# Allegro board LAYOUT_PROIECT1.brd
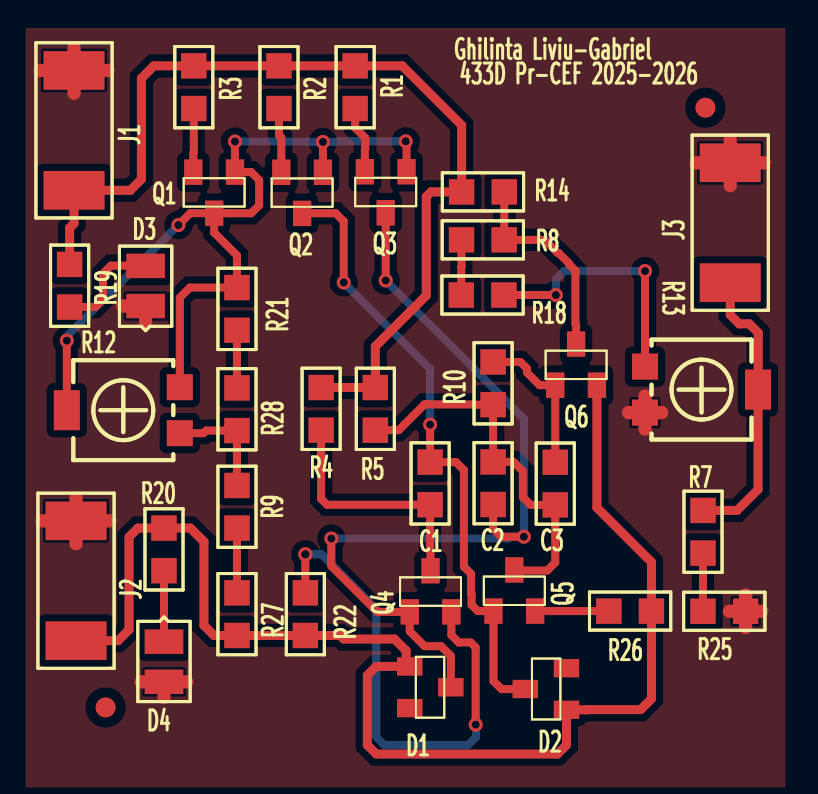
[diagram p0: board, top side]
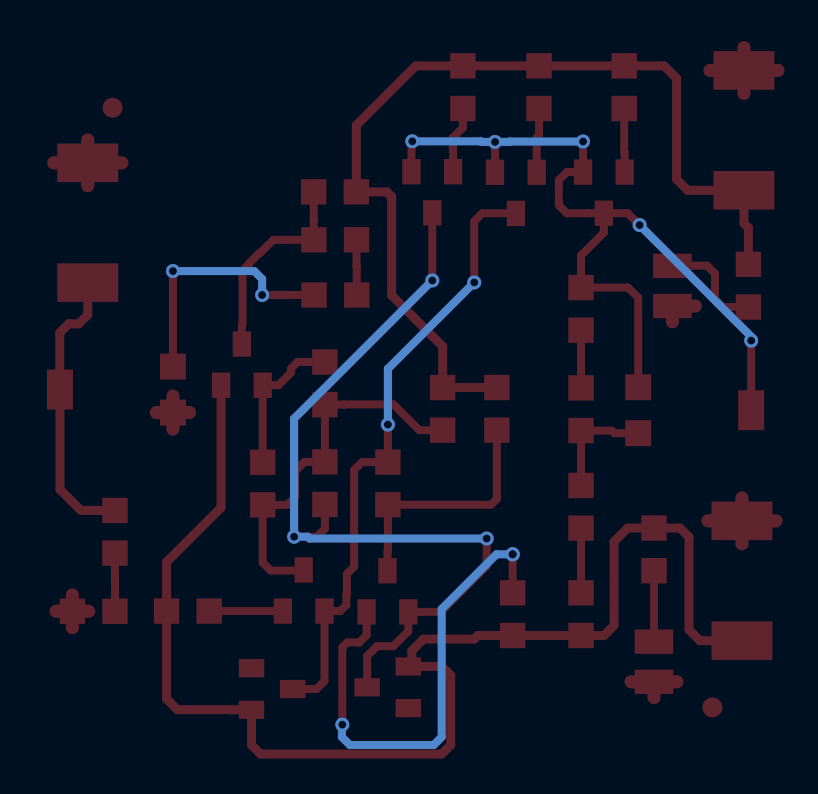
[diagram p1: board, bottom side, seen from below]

No outline. copper layers: TOP, BOTTOM. Coordinates in mm from the lowest, leftmost part position.

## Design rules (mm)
nets with their own width: min track width 0.4; nets N103383 N103451 N103463 N103557 N103581 N103587 N103701 N103715 N103835 N103897 N103911 N103917 N104055 N104249 N104493 N105640 N1034391 N1036391 N1041651 N1042051
nets with their own width: min track width 0.45; nets OUT+ V+ V-
nets with their own width: min track width 0.66; nets GND

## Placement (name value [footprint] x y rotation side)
C1  2.2n  [SMC0805]  18.03 10.26 90 top
C2  2.2n  [SMC0805]  21.18 10.27 90 top
C3  100p  [SMC0805]  24.29 10.25 90 top
D1  BZX84-C5V6  [TO236AA]  17.01 2.17 180 top
D2  BZX84-C5V6  [TO236AA]  24.85 0 0 top
D3  5V,LED,LED  [SMD0805]  3.8 20.2 90 top
D4  5V,LED,LED  [SMD0805]  4.72 3.41 270 top
J1  CON2  [SMR2512]  0.22 25.99 90 top
J2  CON2  [SMR2512]  0.32 3.46 90 top
J3  CON2  [SMR2512]  33.04 21.37 90 top
NOREF  -  [unnamed]  1.8 0.12 0 top
NOREF#2  -  [unnamed]  31.8 30.12 0 top
Q1  QBC856B  [TO236AA]  8.27 26.9 90 top
Q2  QBC856B  [TO236AA]  12.67 26.89 90 top
Q3  QBC856B  [TO236AA]  16.85 26.92 90 top
Q4  QBC846B  [TO236AA]  17.01 4.9 270 top
Q5  QBC846B  [TO236AA]  21.2 4.94 270 top
Q6  QBC846B  [TO236AA]  24.29 16.24 270 top
R1  2k  [SMR0805]  14.28 30.08 90 top
R2  2k  [SMR0805]  10.47 30.08 90 top
R3  1.5k  [SMR0805]  6.21 30.08 90 top
R4  2k  [SMR0805]  12.58 13.99 90 top
R5  2k  [SMR0805]  15.29 13.99 90 top
R7  15k  [SMR0805]  31.68 7.84 90 top
R8  9.1k  [SMR0805]  19.6 23.51 0 top
R9  15k  [SMR0805]  8.37 9.09 90 top
R10  10k  [SMR0805]  21.18 17.4 270 top
R12  500k  [TS53YL]  5.51 16.14 0 top
R13  10K  [TS53YL]  28.78 14.87 180 top
R14  2k  [SMR0805]  21.74 25.91 180 top
R18  10k  [SMR0805]  21.72 20.75 180 top
R19  220  [SMR0805]  0 20.15 90 top
R20  220  [SMR0805]  4.72 6.96 90 top
R21  150k  [SMR0805]  8.37 18.99 90 top
R22  33  [SMR0805]  11.79 3.72 90 top
R25  1k  [SMR0805]  33.81 4.93 180 top
R26  33  [SMR0805]  29.1 4.94 180 top
R27  2.7k  [SMR0805]  8.37 3.72 90 top
R28  10k  [SMR0805]  8.37 13.97 90 top

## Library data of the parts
C1-C3 = C
D1 D2 = BZX84-C5V6_9
D3 D4 = LED_5
J1-J3 = CON2
Q1-Q3 = QBC856B_0
Q4-Q6 = QBC846B_0
R1-R5 R7-R10 R14 R18-R22 R25-R28 = R
R12 R13 = POT_0

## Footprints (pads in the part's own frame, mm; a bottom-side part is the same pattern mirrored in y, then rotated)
SMC0805
  rect 1.27x1.27 smd: 1(0,0) 2(2.134,0)
SMD0805
  rect 1.219x1.93 smd: A(2.007,0) C(0,0)
SMR0805
  rect 1.27x1.27 smd: 1(0,0) 2(2.134,0)
SMR2512
  rect 1.93x3.048 smd: 1(0,0) 2(5.994,0)
TO236AA
  rect 1.27x0.914 smd: 1(0,0) 2(0,2.083) 3(-2.057,1.041)
TS53YL
  rect 1.3x1.3 smd: 1(0,0) 3(0,-2.3)
  rect 1.3x2 smd: 2(-5.65,-1.15)
unnamed
  round 1 smd: (0,0)

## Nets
GND: D3.C D4.A J1.2 J2.2 J3.2 R13.1 R25.1
OUT+: J3.1 R7.2 R13.2(WIPER)
V+: J1.1 R1.2 R2.2 R3.2 R4.2 R5.2 R14.2 R19.2
V-: D1.1 D2.1 J2.1 Q6.2(E) R20.2 R22.1 R26.1 R27.1
N103383: D3.A R19.1
N103451: Q3.2(E) R1.1
N103463: Q2.2(E) R2.1
N103557: Q1.1 Q1.3 Q2.1 Q3.1 R12.1 R12.2(WIPER) R21.2
N103581: C1.2 D2.3(C) Q2.3 Q5.1
N103587: C2.1 D1.3(C) Q3.3 Q4.1
N103701: Q6.3 R8.2 R14.1
N103715: R13.3 R18.1
N103835: R21.1 R28.2
N103897: C2.2 C3.1 Q5.3 R5.1 R10.2
N103911: R9.2 R12.3 R28.1
N103917: C1.1 Q4.3 R4.1
N104055: C3.2 Q6.1 R10.1
N104249: R7.1 R25.2
N104493: D4.C R20.1
N105640: Q4.2(E) R22.2
N1034391: Q1.2(E) R3.1
N1036391: R8.1 R18.2
N1041651: Q5.2(E) R26.2
N1042051: R9.1 R27.2

Pads without a net: D1 2; D2 2

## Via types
v1: diameter 0.7, hole 0.4, TOP to BOTTOM, 15 vias

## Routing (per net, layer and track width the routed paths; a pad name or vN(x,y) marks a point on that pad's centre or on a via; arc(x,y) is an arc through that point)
GND: length 28.6
  TOP w0.66: 31.34,27.36 J3.2 ; J3.2 34.74,27.36 ; J3.2 33.04,28.51 ; J3.2 33.04,26.22 ; 0.22,30.84 J1.2 ; J1.2 1.92,31.98 ; J1.2 0.22,33.13 ; J1.2 -1.48,31.98 ; R13.1 29.61,14.87 ; R13.1 28.78,14.04 ; R13.1 27.95,14.87 ; R13.1 28.78,15.7 ; -1.38,9.45 J2.2 ; J2.2 2.02,9.45 ; J2.2 0.32,8.31 ; J2.2 0.32,10.6 ; D4.A 5.86,1.4 ; D4.A 4.72,0.62 ; D4.A 3.58,1.4 ; 2.66,20.2 D3.C 3.8,19.41 ; 33,4.93 R25.1 ; R25.1 33.81,4.12 ; R25.1 34.62,4.93 ; R25.1 33.81,5.74
OUT+: length 14.4
  TOP w0.45: J3.1 33.04,19.76 33.49,19.31 33.99,19.31 34.44,18.86 34.44,16.03 R13.2 34.43,11.02 33.38,9.97 R7.2
V+: length 48.5
  TOP w0.45: R19.2 0,24.11 0.22,24.33 J1.1 3.04,25.99 3.59,26.54 3.59,31.59 4.21,32.21 R3.2 R2.2 R1.2 16.64,32.21 19.61,29.24 R14.2 18.08,25.91 17.84,25.67 17.84,20.73 15.29,18.18 R5.2 R4.2
V-: length 66.5
  TOP w0.45: D1.1 16.83,2.17 ; 16.83,2.17 16.83,2.96 16.25,3.54 13.71,3.54 13.53,3.72 R22.1 R27.1 7.22,3.72 6.72,4.22 6.72,8.41 6.04,9.09 R20.2 3.42,9.09 2.97,8.64 2.97,4.01 2.42,3.46 J2.1 ; 16.83,2.17 15.33,2.17 14.89,1.73 14.89,-1.76 15.34,-2.21 24.4,-2.21 24.85,-1.76 D2.1 25.84,0 25.85,0.01 28.56,0.01 29.1,0.55 R26.1 29.1,7.39 26.37,10.12 Q6.2
N103383: length 5.4
  TOP w0.4: D3.A 3.79,22.22 2.07,22.22 1.67,21.82 1.67,20.55 1.27,20.15 R19.1
N103451: length 3.4
  TOP w0.4: R1.1 14.28,29.12 14.79,28.61 14.79,28.06 14.77,28.04 Q3.2
N103463: length 3.2
  TOP w0.4: R2.1 10.47,28.75 10.59,28.63 Q2.2
N103557: length 43.5
  TOP w0.4: v1(5.44,24.25) 6.03,24.84 Q1.3 ; Q1.3 7.23,23.87 8.37,22.73 R21.2 6.02,21.12 5.51,20.62 R12.1 ; Q1.3 8.01,24.84 8.02,24.84 9.08,24.84 9.48,25.24 9.48,26.5 9.08,26.9 Q1.1 v1(8.27,28.43) ; v1(-0.14,18.47) R12.2 ; v1(12.67,28.41) Q2.1 ; v1(16.81,28.44) 16.85,28.4 Q3.1
  BOTTOM w0.4: v1(8.27,28.43) 11.95,28.43 11.97,28.41 v1(12.67,28.41) 13.35,28.41 13.38,28.44 v1(16.81,28.44) ; v1(-0.14,18.47) -0.14,18.67 v1(5.44,24.25)
N103581: length 31.3
  TOP w0.4: D2.3 22.79,1.04 21.6,1.04 21.2,1.44 Q5.1 20.42,4.94 20.11,5.25 20.11,5.76 20.08,5.79 20.08,6.8 19.72,7.16 19.72,11.99 19.32,12.39 C1.2 v1(18.03,14.27) ; v1(13.71,21.38) 13.71,24.44 13.31,24.84 11.64,24.84 Q2.3
  BOTTOM w0.4: v1(13.71,21.38) 18.03,17.06 v1(18.03,14.27)
N103587: length 43
  TOP w0.4: v1(22.72,8.66) 21.58,8.66 21.18,9.06 C2.1 ; Q3.3 v1(15.81,21.48) ; D1.3 19.07,2.69 18.58,3.18 17.76,3.18 17.01,3.93 Q4.1 15.38,4.9 13.09,7.19 v1(13.09,8.57)
  BOTTOM w0.4: v1(13.09,8.57) 21.95,8.57 22.04,8.66 v1(22.72,8.66) 22.72,14.57 v1(15.81,21.48)
N103701: length 10.3
  TOP w0.4: R14.1 21.74,24.48 21.73,24.47 R8.2 23.76,23.51 24.41,22.86 24.45,22.86 24.98,22.32 24.98,22.29 25.3,21.97 25.3,19.29 25.33,19.26 Q6.3
N103715: length 12.8
  TOP w0.4: R18.1 v1(24.32,20.75) ; v1(28.78,21.95) R13.3
  BOTTOM w0.4: v1(28.78,21.95) 24.72,21.95 24.32,21.55 v1(24.32,20.75)
N103835: length 2.9
  TOP w0.4: R21.1 R28.2
N103897: length 19.2
  TOP w0.4: Q5.3 22.27,6.97 23.89,6.97 24.29,7.37 C3.1 23.06,10.25 22.67,10.64 22.67,11.93 22.2,12.4 C2.2 R10.2 20.22,15.27 20.2,15.28 17.75,15.28 16.46,13.99 R5.1
N103911: length 5.7
  TOP w0.4: R9.2 R28.1 6.83,13.97 6.7,13.84 R12.3
N103917: length 12.3
  TOP w0.4: Q4.3 18.05,7.92 18.03,7.94 C1.1 12.87,10.26 12.58,10.55 R4.1
N104055: length 7.6
  TOP w0.4: R10.1 22.55,17.4 22.88,17.07 22.88,16.87 23.51,16.24 Q6.1 C3.2
N104249: length 2.9
  TOP w0.4: R7.1 31.68,6.51 31.68,6.51 R25.2
N104493: length 3.6
  TOP w0.4: R20.1 D4.C
N105640: length 25.5
  TOP w0.4: v1(20.31,-0.74) 20.31,3.12 20.06,3.37 19.46,3.37 19.09,3.74 Q4.2 ; R22.2 v1(11.79,7.78)
  BOTTOM w0.4: v1(11.79,7.78) 12.6,7.78 15.34,5.04 15.34,-1.36 15.74,-1.76 19.93,-1.76 20.33,-1.36 20.33,-0.76 v1(20.31,-0.74)
N1034391: length 3.2
  TOP w0.4: Q1.2 6.19,27.86 6.21,27.88 R3.1
N1036391: length 2.8
  TOP w0.4: R8.1 19.6,22.18 19.59,22.17 R18.2
N1041651: length 3.7
  TOP w0.4: Q5.2 R26.2
N1042051: length 3.2
  TOP w0.4: R9.1 R27.2

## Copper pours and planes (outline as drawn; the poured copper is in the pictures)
GND on TOP: -2.2,-3.88 -2.2,34.11 35.8,34.11 35.8,-3.88 ; 9 cut-outs

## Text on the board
Ref Des/Silkscreen Top: Ghilinta Liviu-Gabriel | 433D Pr-CEF 2025-2026
MECANIC: *  SURFACE | L1 TOP CONDUCTOR | *  DIELECTRIC | L2 BOTTOM CONDUCTOR | DESIGN CROSS SECTION CHART | ___________________________ | TOTAL THICKNESS 1.6 MM | 1-2 | FIGURE | FINISHED_SIZE | 0.4 | DRILL CHART: TOP to BOTTOM | ALL UNITS ARE IN MILLIMETERS | PLATED | QTY | 15 | TOTAL HOLES:
